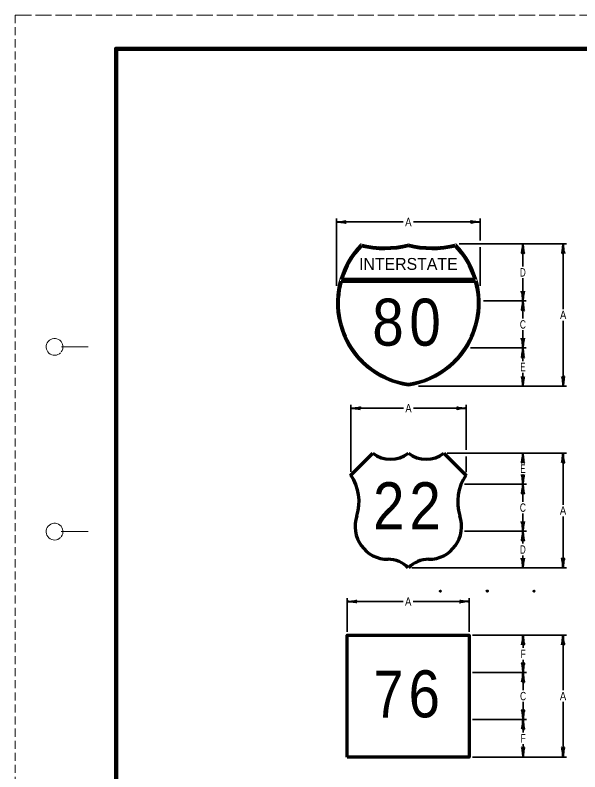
# Model space of a CAD drawing. Extents: x -55 to 625, y -354 to 86.
# Drawn here: x -54.9 to 113.3, y -138.9 to 86.4 of the extents above; entities that cross this region are included whole.
import ezdxf
from ezdxf.enums import TextEntityAlignment as Align

# ---------------------------------------------------------------- set-up
doc = ezdxf.new("R2010")
doc.units = 0
doc.header["$LTSCALE"] = 0.8
doc.header["$PDMODE"] = 32
doc.header["$PDSIZE"] = 0.4
doc.linetypes.add('LONG_DASHED', pattern=[7.5, 6, -1.5])
doc.linetypes.add('MEDIUM_DASHED', pattern=[4.5, 3, -1.5])
doc.layers.add('1', color=7, linetype='Continuous', lineweight=40)
doc.layers.add('61', color=7, linetype='Continuous', lineweight=35)

msp = doc.modelspace()

# ---------------------------------------------------------------- linework, layer by layer
at = {"layer": '1', "linetype": 'MEDIUM_DASHED', "lineweight": 13}
msp.add_line((-54.8373, 86.3965), (-54.8973, -353.6435), dxfattribs=at)
at = {"layer": '1', "lineweight": 35}
for p, q in [((40.8038, 5.8185), (40.8038, 25.8185)), ((40.8038, 24.8185), (60.7308, 24.8185)), ((63.7308, 24.8185), (83.6577, 24.8185)), ((83.6577, 19.3281), (83.6577, 25.8185)), ((77.3485, 18.3281), (109.3485, 18.3281)), ((96.3485, 11.5781), (96.3485, 18.3281)), ((108.3485, 18.3281), (108.3485, -1.0984)), ((83.6577, 5.8185), (83.6577, 17.3281)), ((96.3485, 1.3281), (96.3485, 8.0781)), ((84.6497, 1.3281), (97.3485, 1.3281)), ((96.3485, 1.3281), (96.3485, -3.9219)), ((108.3485, -4.5984), (108.3485, -24.0249)), ((80.7855, -12.6719), (97.3485, -12.6719)), ((96.3485, -20.0984), (96.3485, -24.0249)), ((65.2308, -24.0249), (109.3485, -24.0249)), ((45.1216, -49.5757), (45.1216, -29.6416)), ((45.1216, -30.6416), (60.7787, -30.6416)), ((63.7787, -30.6416), (79.4358, -30.6416)), ((79.4358, -43.0249), (79.4358, -29.6416)), ((73.8191, -44.0249), (109.3088, -44.0249)), ((79.4358, -49.6416), (79.4358, -45.0249)), ((96.3485, -46.8661), (96.3485, -44.0249)), ((108.3088, -44.0249), (108.3088, -59.3466)), ((96.3485, -53.2072), (96.3485, -50.3661)), ((97.4042, -53.2072), (78.9218, -53.2072)), ((96.3485, -53.2072), (96.3485, -58.4572)), ((108.3088, -62.8466), (108.3088, -78.1682)), ((97.4042, -67.2073), (79.0058, -67.2073)), ((96.3485, -74.4377), (96.3485, -78.1682)), ((63.2706, -78.1682), (109.3088, -78.1682)), ((44.0411, -97.1682), (44.0411, -87.1682)), ((80.3411, -97.1682), (80.3411, -87.1682)), ((44.0411, -88.1682), (60.6911, -88.1682)), ((63.6911, -88.1682), (80.3411, -88.1682)), ((81.3411, -98.1682), (109.3088, -98.1682)), ((96.4042, -101.9932), (96.4042, -98.1682)), ((108.3088, -98.1682), (108.3088, -114.5682)), ((96.4042, -109.3182), (96.4042, -105.4932)), ((81.3411, -109.3182), (97.4042, -109.3182)), ((96.4042, -109.3182), (96.4042, -114.5682)), ((108.3088, -118.0682), (108.3088, -134.4682)), ((81.3411, -123.3182), (97.4042, -123.3182)), ((96.4042, -130.6432), (96.4042, -134.4682)), ((81.3411, -134.4682), (109.3088, -134.4682))]:
    msp.add_line(p, q, dxfattribs=at)
at = {"layer": '1', "lineweight": 70}
for p, q in [((42.2178, 7.2157), (82.2438, 7.2157)), ((82.0922, 7.7397), (42.3693, 7.7397)), ((45.0261, -50.6416), (51.6424, -44.0252)), ((72.8189, -44.0252), (79.4358, -50.6416))]:
    msp.add_line(p, q, dxfattribs=at)
at = {"layer": '1', "lineweight": 35}
for points in [[(96.3485, -7.4219), (96.3485, -12.6719), (96.3485, -16.5984)], [(96.3485, -61.9572), (96.3485, -67.2073), (96.3485, -70.9377)], [(96.4042, -118.0682), (96.4042, -123.3182), (96.4042, -127.1432)]]:
    msp.add_lwpolyline(points, dxfattribs=at)
at = {"layer": '1', "lineweight": 70}
msp.add_lwpolyline([(44.0411, -134.4682), (44.0411, -98.1682), (80.3411, -98.1682), (80.3411, -134.4682)], close=True, dxfattribs=at)
at = {"layer": '1', "lineweight": 13}
for centre, radius, start, end in [((65.7602, 0.681), 24.9568, 135, 261.8699), ((55.172, 46.1223), 28.6765, 255.74997, 284.25003), ((69.2896, 46.1223), 28.6765, 255.74997, 284.25003), ((58.7014, 0.681), 24.9568, 278.1301, 45)]:
    msp.add_arc(centre, radius, start, end, dxfattribs=at)
at = {"layer": '1', "lineweight": 70}
for centre, radius, start, end in [((65.7602, 0.681), 24.4326, 135.69236, 163.20725), ((55.172, 46.1223), 29.2006, 256.3405, 283.98896), ((69.2896, 46.1223), 29.2006, 256.01104, 283.6595), ((58.7014, 0.681), 24.4326, 16.79275, 44.30764), ((65.7602, 0.681), 24.4326, 164.48686, 261.8699), ((58.7014, 0.681), 24.4326, 278.1301, 15.51314), ((56.9367, -36.9646), 8.8248, 233.13599, 306.864), ((67.525, -36.9646), 8.8248, 233.136, 306.86401), ((33.8236, -58.3622), 13.7213, 341.82892, 34.57472), ((90.638, -58.3622), 13.7213, 145.42527, 198.17107), ((56.1816, -65.7688), 9.8315, 161.45202, 269.9953), ((68.2801, -65.7688), 9.8315, 270.0047, 18.54798), ((56.1808, -83.9173), 8.3172, 43.72746, 90), ((68.2809, -83.9173), 8.3172, 90, 136.27254)]:
    msp.add_arc(centre, radius, start, end, dxfattribs=at)
at = {"layer": '1'}
for centre, major_axis, ratio, start_param, end_param in [((41.9243, 24.6069), (-1.7565, 0.1757), 0.07063, 3.14071475, 5.41810995), ((41.895, 25.0948), (-1.7857, -0.1562), 0.122415, 0.89635335, 3.14159265), ((82.5666, 24.5422), (1.7857, 0.1562), 0.122415, 0.89635335, 3.14159265), ((82.5666, 24.5422), (1.7857, 0.1562), 0.122415, 0.89635335, 3.14159265), ((82.5372, 25.0301), (1.7565, -0.1757), 0.07063, 3.14071475, 5.41810995), ((82.5372, 25.0301), (1.7565, -0.1757), 0.07063, 3.14071475, 5.41810995), ((96.1369, 17.2076), (0.1757, 1.7565), 0.07063, 3.14071475, 5.41810995), ((96.1369, 17.2076), (0.1757, 1.7565), 0.07063, 3.14071475, 5.41810995), ((96.6248, 17.2369), (-0.1562, 1.7857), 0.122415, 0.89635335, 3.14159265), ((96.6248, 17.2369), (-0.1562, 1.7857), 0.122415, 0.89635335, 3.14159265), ((108.1369, 17.2076), (0.1757, 1.7565), 0.07063, 3.14071475, 5.41810995), ((108.1369, 17.2076), (0.1757, 1.7565), 0.07063, 3.14071475, 5.41810995), ((108.6248, 17.2369), (-0.1562, 1.7857), 0.122415, 0.89635335, 3.14159265), ((108.6248, 17.2369), (-0.1562, 1.7857), 0.122415, 0.89635335, 3.14159265), ((96.0722, 2.4193), (0.1562, -1.7857), 0.122415, 0.89635335, 3.14159265), ((96.0722, 2.4193), (0.1562, -1.7857), 0.122415, 0.89635335, 3.14159265), ((96.5601, 2.4486), (-0.1757, -1.7565), 0.07063, 3.14071475, 5.41810995), ((96.5601, 2.4486), (-0.1757, -1.7565), 0.07063, 3.14071475, 5.41810995), ((96.1369, 0.2076), (0.1757, 1.7565), 0.07063, 3.14071475, 5.41810995), ((96.1369, 0.2076), (0.1757, 1.7565), 0.07063, 3.14071475, 5.41810995), ((96.6248, 0.2369), (-0.1562, 1.7857), 0.122415, 0.89635335, 3.14159265), ((96.6248, 0.2369), (-0.1562, 1.7857), 0.122415, 0.89635335, 3.14159265), ((96.0722, -11.5807), (0.1562, -1.7857), 0.122415, 0.89635335, 3.14159265), ((96.0722, -11.5807), (0.1562, -1.7857), 0.122415, 0.89635335, 3.14159265), ((96.5601, -11.5514), (-0.1757, -1.7565), 0.07063, 3.14071475, 5.41810995), ((96.5601, -11.5514), (-0.1757, -1.7565), 0.07063, 3.14071475, 5.41810995), ((96.1369, -13.7924), (0.1757, 1.7565), 0.07063, 3.14071475, 5.41810995), ((96.1369, -13.7924), (0.1757, 1.7565), 0.07063, 3.14071475, 5.41810995), ((96.6248, -13.7631), (-0.1562, 1.7857), 0.122415, 0.89635335, 3.14159265), ((96.6248, -13.7631), (-0.1562, 1.7857), 0.122415, 0.89635335, 3.14159265), ((96.0722, -22.9337), (0.1562, -1.7857), 0.122415, 0.89635335, 3.14159265), ((96.0722, -22.9337), (0.1562, -1.7857), 0.122415, 0.89635335, 3.14159265), ((96.5601, -22.9044), (-0.1757, -1.7565), 0.07063, 3.14071475, 5.41810995), ((96.5601, -22.9044), (-0.1757, -1.7565), 0.07063, 3.14071475, 5.41810995), ((108.0722, -22.9337), (0.1562, -1.7857), 0.122415, 0.89635335, 3.14159265), ((108.0722, -22.9337), (0.1562, -1.7857), 0.122415, 0.89635335, 3.14159265), ((108.5601, -22.9044), (-0.1757, -1.7565), 0.07063, 3.14071475, 5.41810995), ((108.5601, -22.9044), (-0.1757, -1.7565), 0.07063, 3.14071475, 5.41810995), ((46.2421, -30.8532), (-1.7565, 0.1757), 0.07063, 3.14071475, 5.41810995), ((46.2421, -30.8532), (-1.7565, 0.1757), 0.07063, 3.14071475, 5.41810995), ((46.2128, -30.3653), (-1.7857, -0.1562), 0.122415, 0.89635335, 3.14159265), ((46.2128, -30.3653), (-1.7857, -0.1562), 0.122415, 0.89635335, 3.14159265), ((78.3446, -30.9179), (1.7857, 0.1562), 0.122415, 0.89635335, 3.14159265), ((78.3153, -30.43), (1.7565, -0.1757), 0.07063, 3.14071475, 5.41810995), ((96.1369, -45.1454), (0.1757, 1.7565), 0.07063, 3.14071475, 5.41810995), ((96.1369, -45.1454), (0.1757, 1.7565), 0.07063, 3.14071475, 5.41810995), ((96.6248, -45.1161), (-0.1562, 1.7857), 0.122415, 0.89635335, 3.14159265), ((96.6248, -45.1161), (-0.1562, 1.7857), 0.122415, 0.89635335, 3.14159265), ((108.0971, -45.1454), (0.1757, 1.7565), 0.07063, 3.14071475, 5.41810995), ((108.585, -45.1161), (-0.1562, 1.7857), 0.122415, 0.89635335, 3.14159265), ((96.0722, -52.1161), (0.1562, -1.7857), 0.122415, 0.89635335, 3.14159265), ((96.0722, -52.1161), (0.1562, -1.7857), 0.122415, 0.89635335, 3.14159265), ((96.5601, -52.0867), (-0.1757, -1.7565), 0.07063, 3.14071475, 5.41810995), ((96.5601, -52.0867), (-0.1757, -1.7565), 0.07063, 3.14071475, 5.41810995), ((96.1369, -54.3278), (0.1757, 1.7565), 0.07063, 3.14071475, 5.41810995), ((96.1369, -54.3278), (0.1757, 1.7565), 0.07063, 3.14071475, 5.41810995), ((96.6248, -54.2984), (-0.1562, 1.7857), 0.122415, 0.89635335, 3.14159265), ((96.6248, -54.2984), (-0.1562, 1.7857), 0.122415, 0.89635335, 3.14159265), ((96.0722, -66.1161), (0.1562, -1.7857), 0.122415, 0.89635335, 3.14159265), ((96.0722, -66.1161), (0.1562, -1.7857), 0.122415, 0.89635335, 3.14159265), ((96.5601, -66.0867), (-0.1757, -1.7565), 0.07063, 3.14071475, 5.41810995), ((96.5601, -66.0867), (-0.1757, -1.7565), 0.07063, 3.14071475, 5.41810995), ((96.1369, -68.3278), (0.1757, 1.7565), 0.07063, 3.14071475, 5.41810995), ((96.1369, -68.3278), (0.1757, 1.7565), 0.07063, 3.14071475, 5.41810995), ((96.6248, -68.2984), (-0.1562, 1.7857), 0.122415, 0.89635335, 3.14159265), ((96.6248, -68.2984), (-0.1562, 1.7857), 0.122415, 0.89635335, 3.14159265), ((96.0722, -77.077), (0.1562, -1.7857), 0.122415, 0.89635335, 3.14159265), ((96.0722, -77.077), (0.1562, -1.7857), 0.122415, 0.89635335, 3.14159265), ((96.5601, -77.0477), (-0.1757, -1.7565), 0.07063, 3.14071475, 5.41810995), ((96.5601, -77.0477), (-0.1757, -1.7565), 0.07063, 3.14071475, 5.41810995), ((108.0325, -77.077), (0.1562, -1.7857), 0.122415, 0.89635335, 3.14159265), ((108.5204, -77.0477), (-0.1757, -1.7565), 0.07063, 3.14071475, 5.41810995), ((45.1323, -87.8919), (-1.7857, -0.1562), 0.122415, 0.89635335, 3.14159265), ((45.1323, -87.8919), (-1.7857, -0.1562), 0.122415, 0.89635335, 3.14159265), ((79.2206, -87.9566), (1.7565, -0.1757), 0.07063, 3.14071475, 5.41810995), ((79.2206, -87.9566), (1.7565, -0.1757), 0.07063, 3.14071475, 5.41810995), ((45.1616, -88.3798), (-1.7565, 0.1757), 0.07063, 3.14071475, 5.41810995), ((45.1616, -88.3798), (-1.7565, 0.1757), 0.07063, 3.14071475, 5.41810995), ((79.2499, -88.4445), (1.7857, 0.1562), 0.122415, 0.89635335, 3.14159265), ((79.2499, -88.4445), (1.7857, 0.1562), 0.122415, 0.89635335, 3.14159265), ((96.1926, -99.2887), (0.1757, 1.7565), 0.07063, 3.14071475, 5.41810995), ((96.1926, -99.2887), (0.1757, 1.7565), 0.07063, 3.14071475, 5.41810995), ((96.6805, -99.2594), (-0.1562, 1.7857), 0.122415, 0.89635335, 3.14159265), ((96.6805, -99.2594), (-0.1562, 1.7857), 0.122415, 0.89635335, 3.14159265), ((108.0971, -99.2887), (0.1757, 1.7565), 0.07063, 3.14071475, 5.41810995), ((108.0971, -99.2887), (0.1757, 1.7565), 0.07063, 3.14071475, 5.41810995), ((108.585, -99.2594), (-0.1562, 1.7857), 0.122415, 0.89635335, 3.14159265), ((108.585, -99.2594), (-0.1562, 1.7857), 0.122415, 0.89635335, 3.14159265), ((96.1279, -108.227), (0.1562, -1.7857), 0.122415, 0.89635335, 3.14159265), ((96.1279, -108.227), (0.1562, -1.7857), 0.122415, 0.89635335, 3.14159265), ((96.6158, -108.1977), (-0.1757, -1.7565), 0.07063, 3.14071475, 5.41810995), ((96.6158, -108.1977), (-0.1757, -1.7565), 0.07063, 3.14071475, 5.41810995), ((96.1926, -110.4387), (0.1757, 1.7565), 0.07063, 3.14071475, 5.41810995), ((96.1926, -110.4387), (0.1757, 1.7565), 0.07063, 3.14071475, 5.41810995), ((96.6805, -110.4094), (-0.1562, 1.7857), 0.122415, 0.89635335, 3.14159265), ((96.6805, -110.4094), (-0.1562, 1.7857), 0.122415, 0.89635335, 3.14159265), ((96.1279, -122.227), (0.1562, -1.7857), 0.122415, 0.89635335, 3.14159265), ((96.1279, -122.227), (0.1562, -1.7857), 0.122415, 0.89635335, 3.14159265), ((96.6158, -122.1977), (-0.1757, -1.7565), 0.07063, 3.14071475, 5.41810995), ((96.6158, -122.1977), (-0.1757, -1.7565), 0.07063, 3.14071475, 5.41810995), ((96.1926, -124.4387), (0.1757, 1.7565), 0.07063, 3.14071475, 5.41810995), ((96.1926, -124.4387), (0.1757, 1.7565), 0.07063, 3.14071475, 5.41810995), ((96.6805, -124.4094), (-0.1562, 1.7857), 0.122415, 0.89635335, 3.14159265), ((96.6805, -124.4094), (-0.1562, 1.7857), 0.122415, 0.89635335, 3.14159265), ((96.1279, -133.377), (0.1562, -1.7857), 0.122415, 0.89635335, 3.14159265), ((96.1279, -133.377), (0.1562, -1.7857), 0.122415, 0.89635335, 3.14159265), ((96.6158, -133.3477), (-0.1757, -1.7565), 0.07063, 3.14071475, 5.41810995), ((96.6158, -133.3477), (-0.1757, -1.7565), 0.07063, 3.14071475, 5.41810995), ((108.0325, -133.377), (0.1562, -1.7857), 0.122415, 0.89635335, 3.14159265), ((108.5204, -133.3477), (-0.1757, -1.7565), 0.07063, 3.14071475, 5.41810995)]:
    msp.add_ellipse(centre, major_axis=major_axis, ratio=ratio, start_param=start_param, end_param=end_param, dxfattribs=at)
for p in [(71.784, -85.0825), (85.7387, -85.0428), (99.6935, -85.0825)]:
    msp.add_point(p, dxfattribs=at)
at = {"layer": '61', "linetype": 'LONG_DASHED', "lineweight": 13}
msp.add_line((-54.8373, 86.3965), (625.1827, 86.3965), dxfattribs=at)
at = {"layer": '61', "lineweight": 13}
for p, q in [((-41.1173, -12.3635), (-33.1373, -12.3435)), ((-41.1373, -67.3635), (-33.1373, -67.3635))]:
    msp.add_line(p, q, dxfattribs=at)
at = {"layer": '61', "lineweight": 158}
msp.add_lwpolyline([(614.2027, 76.3965), (-24.8373, 76.3965), (-24.8373, -343.6235)], dxfattribs=at)
at = {"layer": '61', "lineweight": 13}
for centre, end in [((-43.1396, -12.3622), 316.23216), ((-43.1396, -67.3622), 315.37577)]:
    msp.add_arc(centre, 2.5, 323.13009, end, dxfattribs=at)

# ---------------------------------------------------------------- texts
at = {"layer": '1'}
for s, width, p in [('A', 0.85, (62.2308, 23.5685)), ('D', 0.7, (96.3485, 8.5781)), ('A', 0.85, (108.3485, -4.0984)), ('C', 0.75, (96.3485, -6.9219)), ('E', 0.7, (96.3485, -19.5984)), ('A', 0.85, (62.2787, -31.8916)), ('E', 0.7, (96.3485, -49.8661)), ('C', 0.75, (96.3485, -61.4572)), ('A', 0.85, (108.3087, -62.3466)), ('D', 0.7, (96.3485, -73.9377)), ('A', 0.85, (62.191, -89.4182)), ('F', 0.75, (96.4041, -104.9932)), ('C', 0.75, (96.4041, -117.5682)), ('A', 0.85, (108.3087, -117.5682)), ('F', 0.75, (96.4041, -130.1432))]:
    msp.add_text(s, height=2.5, dxfattribs=dict(at, width=width)).set_placement(p, align=Align.CENTER)
msp.add_text('INTERSTATE', height=3.529, dxfattribs=at).set_placement((62.2309, 10.5681), align=Align.CENTER)
for s, width, p in [('8', 0.9, (51.4885, -12.0055)), ('0', 0.9, (62.5288, -12.0055)), ('2', 0.9, (51.7163, -66.6733)), ('2', 0.9, (62.5293, -66.6733)), ('7', 0.85, (51.8707, -122.7125)), ('6', 0.9, (62.2888, -122.6577))]:
    msp.add_text(s, height=14, dxfattribs=dict(at, width=width)).set_placement(p)

doc.saveas('drawing.dxf')
